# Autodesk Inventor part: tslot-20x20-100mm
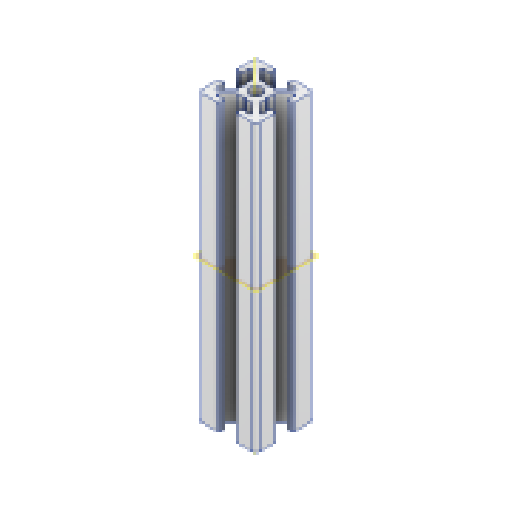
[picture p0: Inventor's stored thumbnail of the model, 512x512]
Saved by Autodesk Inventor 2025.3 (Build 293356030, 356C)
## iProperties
Created: 2025-03
Part Number: tslot-20x20-100mm
Material: Alluminio 6061
Document SubType Name: Modeling
Designer: Ryzen5700u
Density: 2.7 g/cm^3
Appearance: Alluminio - Piatto
Author: Ryzen5700u
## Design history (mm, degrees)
feature "Base1"
sketch "Schizzo1"
  geometry: L1 (3.761, -16)-(4.7, -16) reference; L2 (3.761, -16)-(0.7, -12.939) reference; L3 (0.7, -12.939)-(0.7, -10.52) reference; L4 (0.4, -10)-(0.7, -10.52) reference; L5 (0.4, -10)-(0.7, -9.48) reference; L6 (0.7, -7.061)-(0.7, -9.48) reference; L7 (3.761, -4)-(0.7, -7.061) reference; L8 (3.761, -4)-(4.7, -4) reference; L9 (4.7, -4)-(4.7, -7) reference; L10 (4.7, -7)-(6.4, -7) reference; L11 (6.7, -6.7)-(6.7, -1) reference; L12 (5.7, 0)-(0, 0) reference; L13 (-0.3, -2)-(-0.3, -0.3) reference; L14 (2.7, -2)-(-0.3, -2) reference; L15 (2.7, -2.939)-(2.7, -2) reference; L16 (2.7, -2.939)-(-0.361, -6) reference; L17 (-0.361, -6)-(-2.78, -6) reference; L18 (-3.3, -6.3)-(-2.78, -6) reference; L19 (-3.3, -6.3)-(-3.82, -6) reference; L20 (-6.239, -6)-(-3.82, -6) reference; L21 (-9.3, -2.939)-(-6.239, -6) reference; L22 (-9.3, -2.939)-(-9.3, -2) reference; L23 (-9.3, -2)-(-6.3, -2) reference; L24 (-6.3, -2)-(-6.3, -0.3) reference; L25 (-12.3, 0)-(-6.6, 0) reference; L26 (-13.3, -6.7)-(-13.3, -1) reference; L27 (-11.3, -7)-(-13, -7) reference; L28 (-11.3, -4)-(-11.3, -7) reference; L29 (-10.361, -4)-(-11.3, -4) reference; L30 (-10.361, -4)-(-7.3, -7.061) reference; L31 (-7.3, -7.061)-(-7.3, -9.48) reference; L32 (-7, -10)-(-7.3, -9.48) reference; L33 (-7, -10)-(-7.3, -10.52) reference; L34 (-7.3, -12.939)-(-7.3, -10.52) reference; L35 (-10.361, -16)-(-7.3, -12.939) reference; L36 (-10.361, -16)-(-11.3, -16) reference; L37 (-11.3, -16)-(-11.3, -13) reference; L38 (-11.3, -13)-(-13, -13) reference; L39 (-13.3, -13.3)-(-13.3, -19) reference; L40 (-12.3, -20)-(-6.6, -20) reference; L41 (-6.3, -18)-(-6.3, -19.7) reference; L42 (-9.3, -18)-(-6.3, -18) reference; L43 (-9.3, -17.061)-(-9.3, -18) reference; L44 (-9.3, -17.061)-(-6.239, -14) reference; L45 (-6.239, -14)-(-3.82, -14) reference; L46 (-3.3, -13.7)-(-3.82, -14) reference; L47 (-3.3, -13.7)-(-2.78, -14) reference; L48 (-0.361, -14)-(-2.78, -14) reference; L49 (2.7, -17.061)-(-0.361, -14) reference; L50 (2.7, -17.061)-(2.7, -18) reference; L51 (2.7, -18)-(-0.3, -18) reference; L52 (-0.3, -18)-(-0.3, -19.7) reference; L53 (5.7, -20)-(0, -20) reference; L54 (6.7, -13.3)-(6.7, -19) reference; L55 (4.7, -13)-(6.4, -13) reference; L56 (4.7, -16)-(4.7, -13) reference; C1 r 2.1 at (-3.3, -10) reference; A1 r 0.3 centre (6.4, -6.7) between (6.4, -7) and (6.7, -6.7) reference; A2 r 1 centre (5.7, -1) between (6.7, -1) and (5.7, 0) reference; A3 r 0.3 centre (0, -0.3) between (0, 0) and (-0.3, -0.3) reference; A4 r 0.3 centre (-6.6, -0.3) between (-6.3, -0.3) and (-6.6, 0) reference; A5 r 1 centre (-12.3, -1) between (-12.3, 0) and (-13.3, -1) reference; A6 r 0.3 centre (-13, -6.7) between (-13.3, -6.7) and (-13, -7) reference; A7 r 0.3 centre (-13, -13.3) between (-13, -13) and (-13.3, -13.3) reference; A8 r 1 centre (-12.3, -19) between (-13.3, -19) and (-12.3, -20) reference; A9 r 0.3 centre (-6.6, -19.7) between (-6.6, -20) and (-6.3, -19.7) reference; A10 r 0.3 centre (0, -19.7) between (-0.3, -19.7) and (0, -20) reference; A11 r 1 centre (5.7, -19) between (5.7, -20) and (6.7, -19) reference; A12 r 0.3 centre (6.4, -13.3) between (6.7, -13.3) and (6.4, -13) reference; 1 further point
extrude "Estrusione1" join sketch "Schizzo1" distance "d0" = 90; taper "d1" = 0 deg
node "Piano di lavoro1"
node "Asse di lavoro1"
node "Solido1"
node "Linea chiusa proiettata1"
